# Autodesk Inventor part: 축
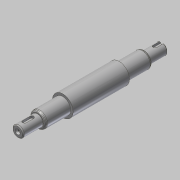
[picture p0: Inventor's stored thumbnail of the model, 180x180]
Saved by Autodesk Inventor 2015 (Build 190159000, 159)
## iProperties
Created: 2019-06
Part Number: 축
Material: 강철, 연강
Document SubType Name: Modeling
Designer: mduedu
Density: 1 g/cm^3
Appearance: 강철
Author: mduedu
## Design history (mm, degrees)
sketch "스케치1"
  geometry: L1 (0, 0)-(21, 0); L2 (21, 0)-(21, 6); L3 (21, 6)-(0, 6); L4 (0, 6)-(0, 0); L5 (21, 0)-(48, 0); L6 (48, 0)-(48, 8.5); L7 (48, 8.5)-(21, 8.5); L8 (21, 8.5)-(21, 0); L9 (48, 0)-(108, 0); L10 (108, 0)-(108, 11); L11 (108, 11)-(48, 11); L12 (48, 11)-(48, 0); L13 (108, 0)-(135, 0); L14 (135, 0)-(135, 8.5); L15 (135, 8.5)-(108, 8.5); L16 (108, 8.5)-(108, 0); L17 (135, 0)-(154, 0); L18 (154, 0)-(154, 6); L19 (154, 6)-(135, 6); L20 (135, 6)-(135, 0)
  constraints: 40 end point, 10 parallel, 5 horizontal, 5 perpendicular
  dimensions: "d3" = 60 distance of L10.end L11.end; "d4" = 17 diameter of L15 L13; "d5" = 22 diameter of L11 L9; "d6" = 17 diameter of L7 L5; "d7" = 12 diameter of L3 L1; "d40" = 19 distance of L18.end L19.end; "d41" = 12 diameter of L19 L17; "d42" = 46 distance between parallel lines of L10 L18; "d43" = 133 distance between parallel lines of L8 L18; "d44" = 154 distance between parallel lines of L4 L18
revolve "회전1" sketch "스케치1" stored, may be unused: angle "d9" = 90 deg
node "작업 평면1"
sketch "스케치2" dims "d10" = 12
  geometry: L1 (3.5, -2)-(-4.5, -2); L2 (-4.5, -2)-(-4.5, 2); L3 (-4.5, 2)-(3.5, 2); L4 (3.5, 2)-(3.5, -2); L5 (-10.5, 8.5)-(-10.5, -8.5) reference; 3 further points
  constraints: 8 end point, 2 midpoint, 2 parallel, 2 vertical alignment, 1 horizontal, 1 horizontal alignment, 1 perpendicular, 4 other
  dimensions: "d12" = 4 dimension on L5; "d13" = 4 distance between parallel lines of L3 L1
extrude "돌출1" cut sketch "스케치2" distance "d14" = 2.5; taper "d15" = 0 deg
sketch "스케치4"
  geometry: L1 (-143.5, 2)-(-135.5, 2); L2 (-135.5, 2)-(-135.5, -2); L3 (-135.5, -2)-(-143.5, -2); L4 (-143.5, -2)-(-143.5, 2); L5 (-143.5, 6)-(-143.5, -6) reference; 2 further points
  constraints: 8 end point, 2 parallel, 1 collinear, 1 horizontal, 1 horizontal alignment, 1 midpoint, 1 perpendicular, 1 vertical alignment, 2 other
  dimensions: "d50" = 10 dimension on L4; "d52" = 4 distance between parallel lines of L1 L3
extrude "돌출2" cut sketch "스케치4" distance "d53" = 2.5; taper "d54" = 0 deg
hole "구멍1" diameter "d18" = 3.242; stored, may be unused: countersink angle "d22" = 90 deg, drill point angle "d24" = 118 deg; dims "d16" = 10, "d17" = 10, "d19" = 8, "d20" = 4, "d21" = 2, "d23" = 10
sketch "스케치3"
  geometry: L1 (0, 0)-(2, 0); L2 (2, 0)-(2, -1.621); L3 (0, -2.776)-(0, 0); L4 (10, -1.621)-(0, -1.621) reference; L5 (0, -2.776)-(2, -1.621)
  constraints: 8 end point, 1 horizontal, 1 parallel, 1 perpendicular, 1 point on line
  dimensions: "d25" = 2 distance between parallel lines of L2 L3; "d27" = 30 deg angle of L1 L5
revolve "회전2" sketch "스케치3" stored, may be unused: angle "d29" = 90 deg
chamfer "모따기1" distance "d30" = 1.82; stored, may be unused: second distance "d31" = 2, angle "d32" = 30 deg
fillet "모깎기1" dims "d36" = 2, "d37" = 1
chamfer "모따기3" distance "d45" = 1.82; stored, may be unused: second distance "d46" = 2, angle "d47" = 30 deg
fillet "모깎기2" dims "d48" = 2, "d49" = 1
chamfer "모따기4" distance "d55" = 1; stored, may be unused: second distance "d56" = 2, angle "d57" = 30 deg
node "솔리드1"
